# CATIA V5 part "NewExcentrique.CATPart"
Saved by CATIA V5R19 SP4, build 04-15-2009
Part number: Excentrique
Bounding box of the stored display mesh (mm): x 10 to 22, y 85 to 115, z 45 to 75
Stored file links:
  C:\Users\Thinkmotion2\Desktop\Pack 1\Retouchés\IAO_2010_1386_abergami\abergami_catiaInitial\ObjetsInitials\NewExcentrique.CATPart
  C:\Users\Thinkmotion2\Desktop\Pack 1\Retouchés\IAO_2010_1386_abergami\abergami_catiaInitial\ObjetsInitials\Product2.CATProduct
  C:\Users\Thinkmotion2\Desktop\Pack 1\Retouchés\IAO_2010_1386_abergami\abergami_catiaInitial\ObjetsInitials\Bati.CATPart
  C:\Users\Thinkmotion2\Desktop\Pack 1\Retouchés\IAO_2010_1386_abergami\abergami_catiaInitial\ObjetsInitials\Squelettedebase.CATPart
  C:\Users\Thinkmotion2\Desktop\Pack 1\Retouchés\IAO_2010_1386_abergami\abergami_catiaInitial\ObjetsInitials\SqueletteExcentrique.CATPart
  C:\Users\Thinkmotion2\Desktop\Pack 1\Retouchés\IAO_2010_1386_abergami\abergami_catiaInitial\ObjetsInitials\SqueletteDoigt.CATPart
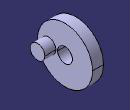
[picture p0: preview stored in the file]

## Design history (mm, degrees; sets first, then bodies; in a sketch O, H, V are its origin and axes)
Parameters
  `Diametre excentrique` = 30 mm
External parameters (linked from other documents)
  External.EpaisseurExcentrique = 6 mm
  External.EpaisseurDoigtExcentrique = 6 mm
  External.DiametreDoigtExcentrique = 8 mm
Set1
  Point1: linked copy from another document
  Plane1: linked copy from another document
  Point2: linked copy from another document
Body1 (main body)
  Sketch1 on Plane1, origin (10, 0, 0), H (0, 1, 0), V (0, 0, 1)
    circle A1 centre (100, 60) radius 15
    point P1 (100, 60)
    reference projected point E1 (100, 60) from Point2
    radius A1 = 15 {= `Diametre excentrique` /2}
    distance P1 E1 = 0
  Pad1: profile Sketch1, direction (1, 0, 0), length 6 {= External.EpaisseurExcentrique}
  Sketch2 on end face of Pad1, origin (16, 0, 0), H (0, 1, 0), V (0, 0, 1)
    circle A1 centre (100, 60) radius 4
    point P1 (100, 60)
    reference projected point E1 (100, 60) from Point2
    radius A1 = 4
    distance P1 E1 = 0
  Pocket1: profile Sketch2, direction (-1, 0, 0), through (limit type 6)
  Sketch3 on end face of Pad1, origin (16, 0, 0), H (0, 1, 0), V (0, 0, 1)
    circle A1 centre (91, 60) radius 4
    point P1 (91, 60)
    reference projected point E1 (91, 60) from Point1
    radius A1 = 4 {= External.DiametreDoigtExcentrique /2}
    distance P1 E1 = 0
  Pad2: profile Sketch3, direction (1, 0, 0), length 6 {= `détruit_LENGTH`}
